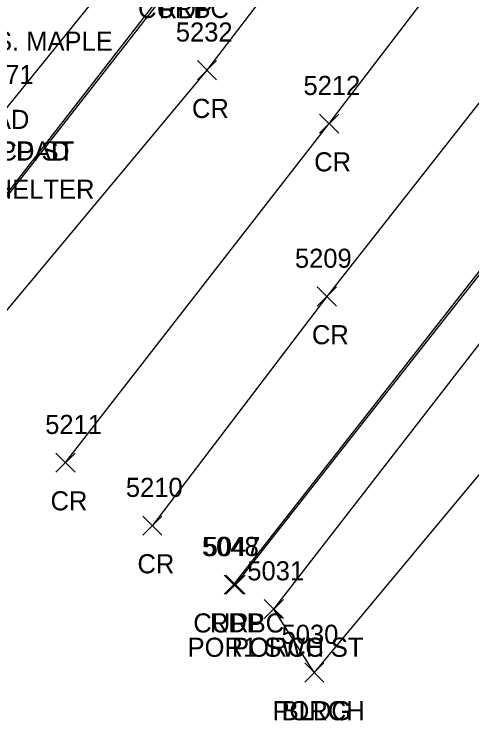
# Model space of a CAD drawing. Extents: x 1618146 to 1620418, y 640749 to 641927.
# Drawn here: x 1620219.4 to 1620267.4, y 640856.8 to 640931.1 of the extents above; entities that cross this region are included whole.
import ezdxf

# ---------------------------------------------------------------- set-up
doc = ezdxf.new("R2010")
doc.units = 0
for name, color, linetype in [('L_A', 7, 'Continuous'), ('L_C', 7, 'Continuous'), ('L_I', 7, 'Continuous'), ('L_TIC', 7, 'Continuous'), ('LBC', 7, 'Continuous'), ('LBF', 7, 'Continuous'), ('P_A', 7, 'Continuous'), ('P_I', 7, 'Continuous'), ('P_TIC', 7, 'Continuous'), ('PET', 7, 'Continuous'), ('PRC', 7, 'Continuous'), ('R_A', 7, 'Continuous'), ('R_C', 7, 'Continuous'), ('R_I', 7, 'Continuous'), ('R_TIC', 7, 'Continuous'), ('RC', 7, 'Continuous'), ('RSW', 7, 'Continuous')]:
    doc.layers.add(name, color=color, linetype=linetype)

msp = doc.modelspace()

# ---------------------------------------------------------------- linework, layer by layer
at = {"layer": 'L_TIC'}
for points in [[(1620245.621, 640867.861), (1620247.621, 640869.861)], [(1620247.621, 640867.861), (1620245.621, 640869.861)], [(1620249.859, 640861.217), (1620251.859, 640863.217)], [(1620251.859, 640861.217), (1620249.859, 640863.217)], [(1620249.859, 640861.217), (1620251.859, 640863.217)], [(1620251.859, 640861.217), (1620249.859, 640863.217)]]:
    msp.add_lwpolyline(points, dxfattribs=at)
at = {"layer": 'LBC'}
msp.add_lwpolyline([(1620332.284, 640856.845), (1620331.644, 640857.534), (1620331.352, 640857.923), (1620308.647, 640877.482), (1620307.781, 640878.325), (1620291.579, 640892.357), (1620287.512, 640896.159), (1620282.611, 640900.197), (1620282.333, 640900.011), (1620250.859, 640862.217)], dxfattribs=at)
at = {"layer": 'LBF'}
msp.add_lwpolyline([(1620250.859, 640862.217), (1620246.621, 640868.861)], dxfattribs=at)
at = {"layer": 'P_TIC'}
for points in [[(1620238.617, 640924.265), (1620240.617, 640926.265)], [(1620240.617, 640924.265), (1620238.617, 640926.265)], [(1620251.423, 640918.672), (1620253.423, 640920.672)], [(1620253.423, 640918.672), (1620251.423, 640920.672)], [(1620251.181, 640900.579), (1620253.181, 640902.579)], [(1620253.181, 640900.579), (1620251.181, 640902.579)], [(1620223.798, 640883.187), (1620225.798, 640885.187)], [(1620225.798, 640883.187), (1620223.798, 640885.187)], [(1620232.904, 640876.595), (1620234.904, 640878.595)], [(1620234.904, 640876.595), (1620232.904, 640878.595)], [(1620241.431, 640870.412), (1620243.431, 640872.412)], [(1620243.431, 640870.412), (1620241.431, 640872.412)]]:
    msp.add_lwpolyline(points, dxfattribs=at)
at = {"layer": 'PET'}
for points in [[(1620359.618, 641102.741), (1620357.552, 641099.276), (1620341.731, 641075.022), (1620339.541, 641071.666), (1620329.909, 641058.991), (1620323.975, 641051.239), (1620317.974, 641043.478), (1620299.64, 641019.571), (1620282.799, 640996.951), (1620281.456, 640995.25), (1620278.195, 640990.782), (1620276.89, 640989.311), (1620275.826, 640987.688), (1620269.888, 640979.335), (1620267.257, 640975.908), (1620246.8, 640948.475), (1620237.104, 640935.681), (1620207.924, 640898.413)], [(1620242.431, 640871.412), (1620272.752, 640910.066), (1620283.046, 640921.534), (1620286.98, 640925.917)]]:
    msp.add_lwpolyline(points, dxfattribs=at)
at = {"layer": 'PRC'}
for points in [[(1620362.761, 641090.181), (1620340.683, 641059.759), (1620325.328, 641039.403), (1620305.343, 641012.417), (1620285.981, 640987.098), (1620282.921, 640982.142), (1620262.646, 640955.357), (1620239.617, 640925.265), (1620211.715, 640891.88)], [(1620224.798, 640884.187), (1620252.423, 640919.672), (1620271.906, 640945.144), (1620290.437, 640967.965), (1620293.935, 640972.261), (1620320.636, 641007.736), (1620341.521, 641037.703), (1620358.234, 641062.028), (1620372.9, 641083.065)], [(1620386.404, 641071.706), (1620361.021, 641035.235), (1620336.241, 641002.906), (1620316.225, 640977.168), (1620300.323, 640960.311), (1620296.609, 640956.784), (1620272.862, 640927.85), (1620252.181, 640901.579), (1620233.904, 640877.595)]]:
    msp.add_lwpolyline(points, dxfattribs=at)
at = {"layer": 'R_TIC'}
for points in [[(1620241.61, 640870.403), (1620243.61, 640872.403)], [(1620243.61, 640870.403), (1620241.61, 640872.403)], [(1620245.621, 640867.861), (1620247.621, 640869.861)], [(1620247.621, 640867.861), (1620245.621, 640869.861)]]:
    msp.add_lwpolyline(points, dxfattribs=at)
at = {"layer": 'RC'}
for points in [[(1620246.343, 640948.761), (1620246.8, 640948.475), (1620236.82, 640935.733), (1620207.783, 640898.448)], [(1620242.61, 640871.403), (1620272.934, 640909.877), (1620283.078, 640921.427), (1620286.98, 640925.917), (1620287.299, 640925.544)]]:
    msp.add_lwpolyline(points, dxfattribs=at)
at = {"layer": 'RSW'}
for points in [[(1620273.827, 640994.382), (1620271.861, 640991.557), (1620269.183, 640988.021), (1620264.777, 640981.848), (1620262.749, 640979.054), (1620260.968, 640976.582), (1620252.715, 640965.558), (1620241.442, 640950.866), (1620232.883, 640938.96), (1620218.2, 640920.806), (1620210.672, 640910.804), (1620202.49, 640900.646)], [(1620246.621, 640868.861), (1620275.079, 640905.51), (1620286.747, 640918.928), (1620290.412, 640922.708), (1620296.264, 640929.294), (1620303.727, 640937.553), (1620301.599, 640941.889)]]:
    msp.add_lwpolyline(points, dxfattribs=at)

# ---------------------------------------------------------------- texts
at = {"layer": 'L_A'}
for s, p in [('CONCPAD', (1620207.64, 640919.119)), ('CONCPAD', (1620211.845, 640915.806)), ('PORCH', (1620242.243, 640863.861)), ('PORCH', (1620246.481, 640857.217)), ('BLDG', (1620247.449, 640857.217))]:
    msp.add_text(s, height=2, dxfattribs=at).set_placement(p)
at = {"layer": 'L_C'}
msp.add_text('S. MAPLE', height=2, dxfattribs=at).set_placement((1620217.415, 640927.312))
at = {"layer": 'L_I'}
for s, p in [('5371', (1620215.507, 640923.806)), ('5031', (1620243.85, 640871.861)), ('5030', (1620247.434, 640865.217)), ('5030', (1620247.434, 640865.217))]:
    msp.add_text(s, height=2, dxfattribs=at).set_placement(p)
at = {"layer": 'P_A'}
for s, p in [('RDP', (1620234.593, 640930.681)), ('CR', (1620238.05, 640920.265)), ('CR', (1620250.856, 640914.672)), ('CR', (1620250.614, 640896.579)), ('CR', (1620223.232, 640879.187)), ('CR', (1620232.337, 640872.595)), ('RDP', (1620239.919, 640866.412))]:
    msp.add_text(s, height=2, dxfattribs=at).set_placement(p)
at = {"layer": 'P_I'}
for s, p in [('5232', (1620236.357, 640928.265)), ('5212', (1620249.73, 640922.672)), ('5209', (1620248.835, 640904.579)), ('5211', (1620222.673, 640887.187)), ('5210', (1620231.124, 640880.595)), ('5048', (1620239.093, 640874.412))]:
    msp.add_text(s, height=2, dxfattribs=at).set_placement(p)
at = {"layer": 'R_A'}
for s, p in [('CURBC', (1620232.403, 640930.733)), ('SWC CPD ST', (1620208.916, 640915.806)), ('CURBC', (1620238.193, 640866.403)), ('POR1 SWC ST', (1620237.59, 640863.861))]:
    msp.add_text(s, height=2, dxfattribs=at).set_placement(p)
at = {"layer": 'R_C'}
msp.add_text('W/ BUS SHELTER', height=2, dxfattribs=at).set_placement((1620205.247, 640911.806))
at = {"layer": 'R_I'}
for s, p in [('5371', (1620215.507, 640923.806)), ('5047', (1620239.271, 640874.403)), ('5031', (1620243.85, 640871.861))]:
    msp.add_text(s, height=2, dxfattribs=at).set_placement(p)

doc.saveas('drawing.dxf')
